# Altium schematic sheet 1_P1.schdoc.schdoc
size 431 x 309 mm; Symbol: Sheet-Symbol_A3; Device: Sheet-Symbol_A3; @Page Name: P1; @Create Date: 2023-12-01; @Page Count: 1; @Page No: 1; @Project Name: TauKeyboard; @Schematic Name: 61key; @Update Date: 2023-12-06; Company: 嘉立创EDA; Page Size: A3; Version: V1.0
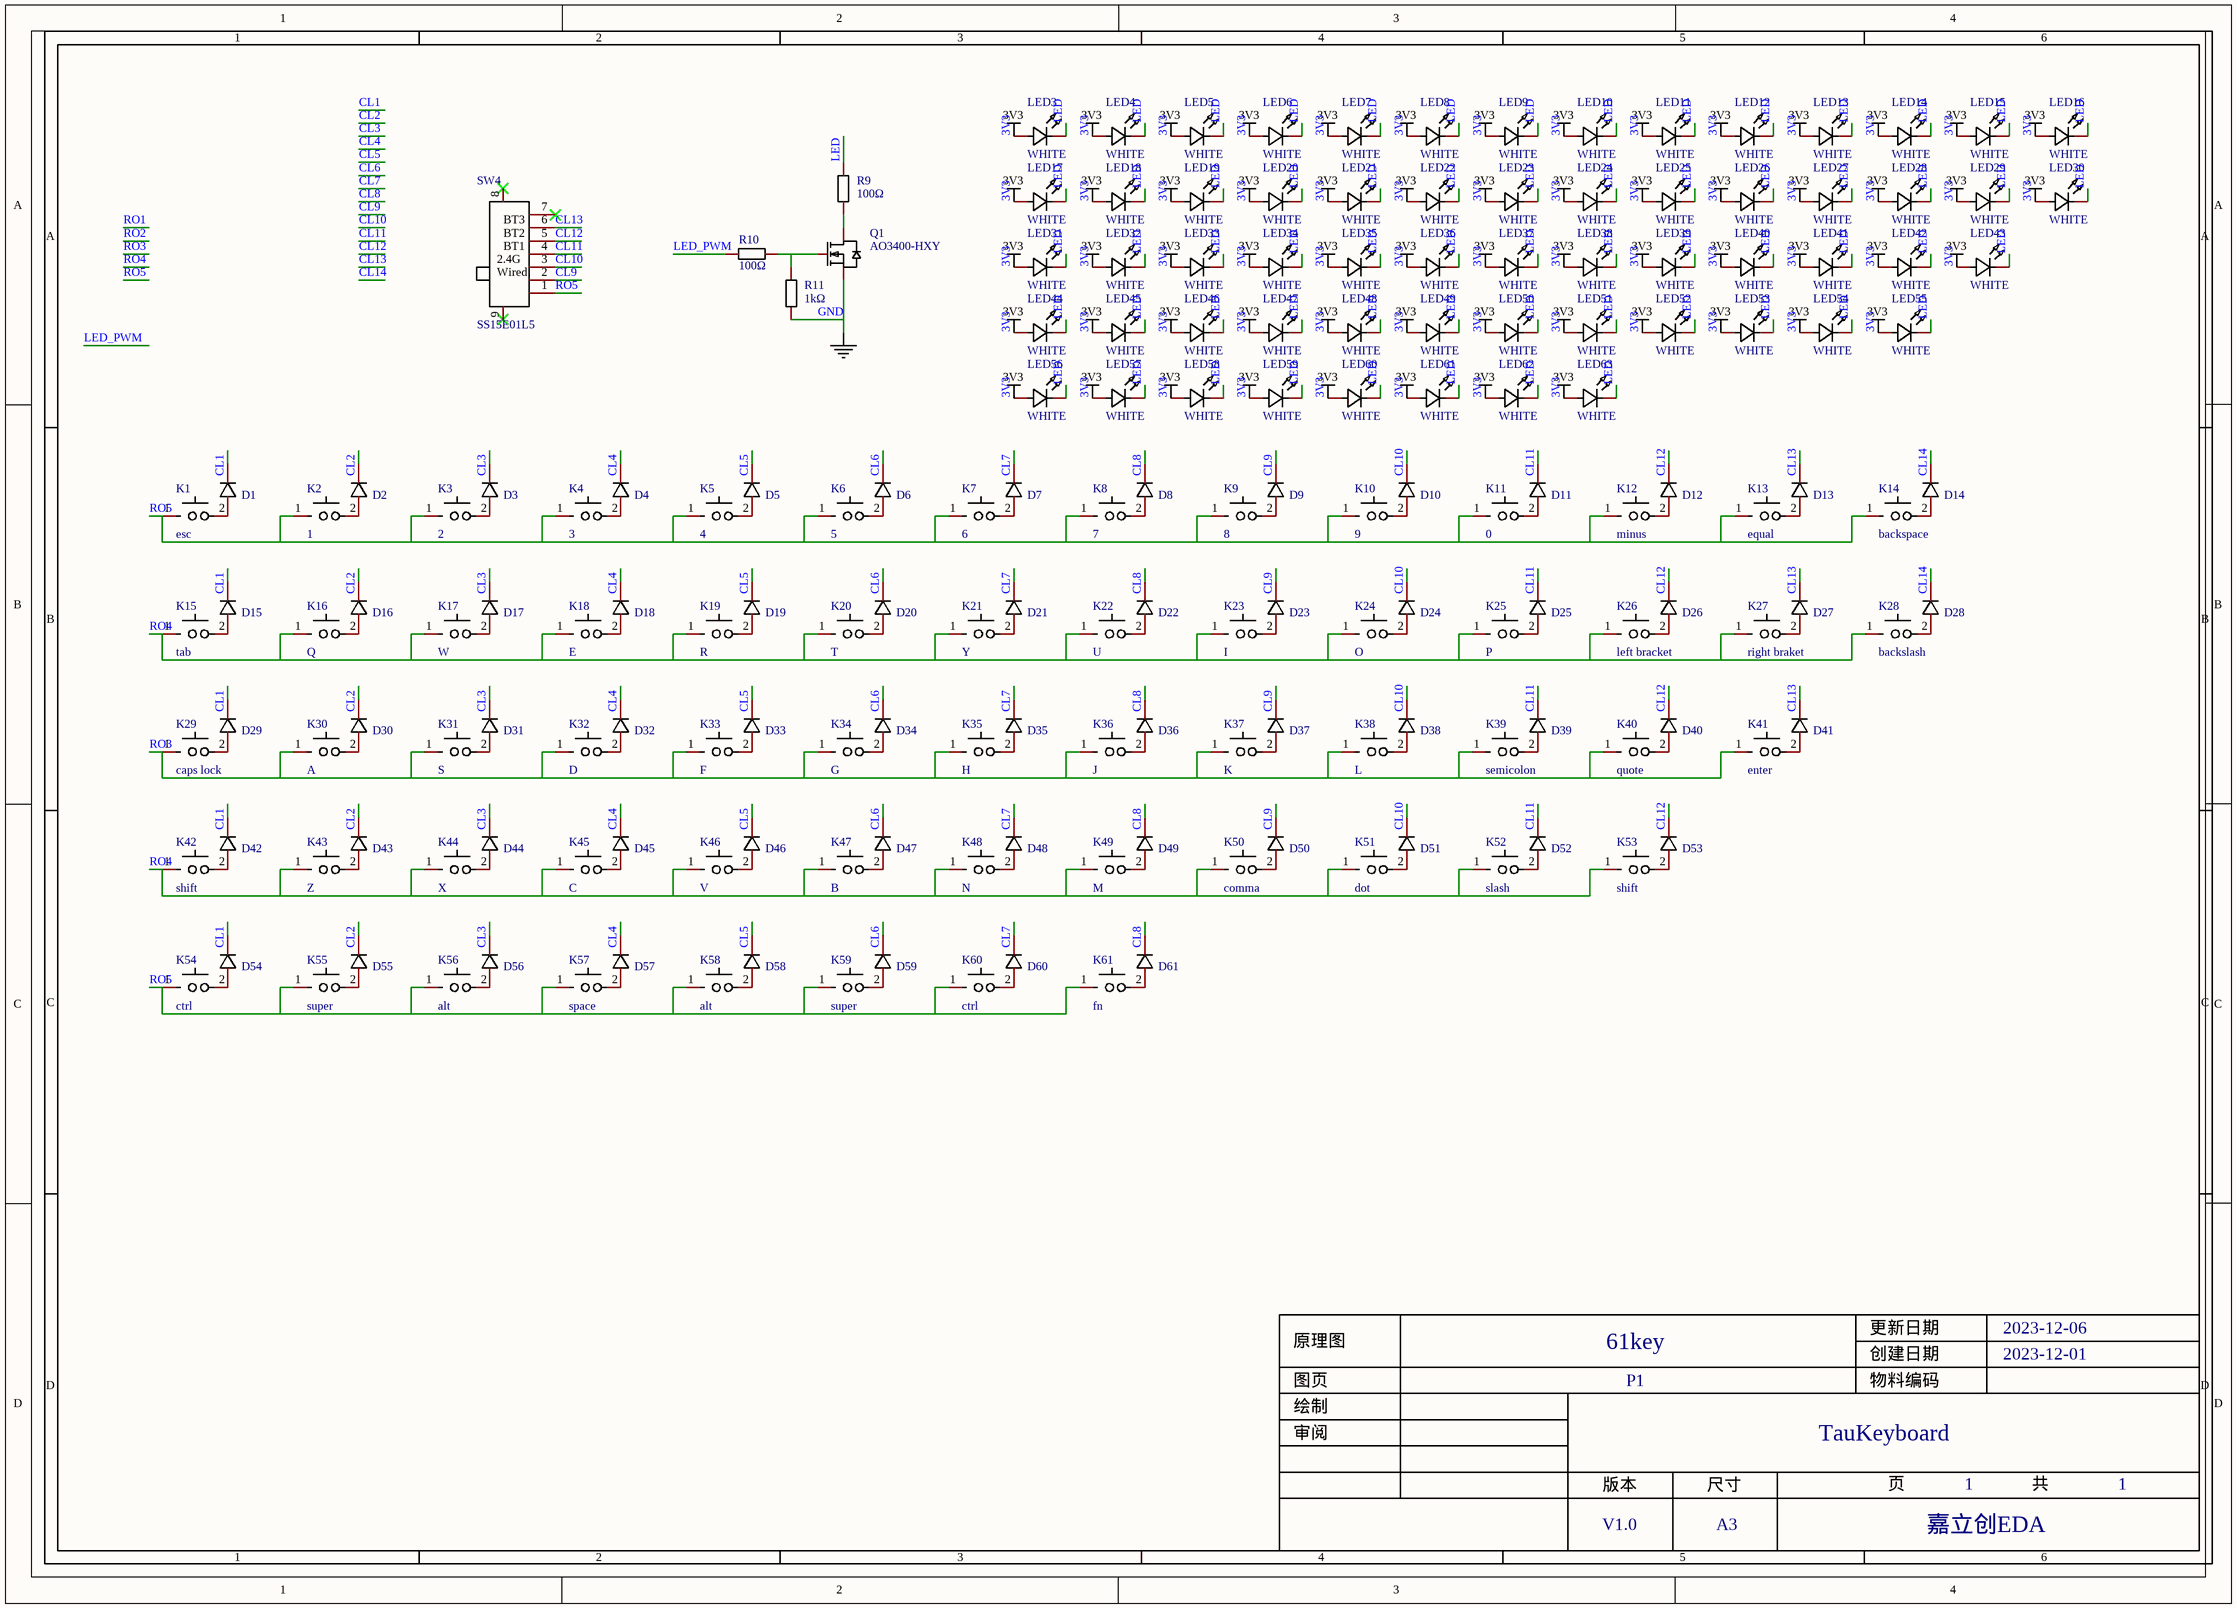
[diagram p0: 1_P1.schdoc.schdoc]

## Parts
D1  1N4148WS_C2128  [SOD-323_L1.8-W1.3-LS2.5-RD]  (value not drawn)
D2  1N4148WS_C2128  [SOD-323_L1.8-W1.3-LS2.5-RD]  (value not drawn)
D3  1N4148WS_C2128  [SOD-323_L1.8-W1.3-LS2.5-RD]  (value not drawn)
D4  1N4148WS_C2128  [SOD-323_L1.8-W1.3-LS2.5-RD]  (value not drawn)
D5  1N4148WS_C2128  [SOD-323_L1.8-W1.3-LS2.5-RD]  (value not drawn)
D6  1N4148WS_C2128  [SOD-323_L1.8-W1.3-LS2.5-RD]  (value not drawn)
D7  1N4148WS_C2128  [SOD-323_L1.8-W1.3-LS2.5-RD]  (value not drawn)
D8  1N4148WS_C2128  [SOD-323_L1.8-W1.3-LS2.5-RD]  (value not drawn)
D9  1N4148WS_C2128  [SOD-323_L1.8-W1.3-LS2.5-RD]  (value not drawn)
D10  1N4148WS_C2128  [SOD-323_L1.8-W1.3-LS2.5-RD]  (value not drawn)
D11  1N4148WS_C2128  [SOD-323_L1.8-W1.3-LS2.5-RD]  (value not drawn)
D12  1N4148WS_C2128  [SOD-323_L1.8-W1.3-LS2.5-RD]  (value not drawn)
D13  1N4148WS_C2128  [SOD-323_L1.8-W1.3-LS2.5-RD]  (value not drawn)
D14  1N4148WS_C2128  [SOD-323_L1.8-W1.3-LS2.5-RD]  (value not drawn)
D15  1N4148WS_C2128  [SOD-323_L1.8-W1.3-LS2.5-RD]  (value not drawn)
D16  1N4148WS_C2128  [SOD-323_L1.8-W1.3-LS2.5-RD]  (value not drawn)
D17  1N4148WS_C2128  [SOD-323_L1.8-W1.3-LS2.5-RD]  (value not drawn)
D18  1N4148WS_C2128  [SOD-323_L1.8-W1.3-LS2.5-RD]  (value not drawn)
D19  1N4148WS_C2128  [SOD-323_L1.8-W1.3-LS2.5-RD]  (value not drawn)
D20  1N4148WS_C2128  [SOD-323_L1.8-W1.3-LS2.5-RD]  (value not drawn)
D21  1N4148WS_C2128  [SOD-323_L1.8-W1.3-LS2.5-RD]  (value not drawn)
D22  1N4148WS_C2128  [SOD-323_L1.8-W1.3-LS2.5-RD]  (value not drawn)
D23  1N4148WS_C2128  [SOD-323_L1.8-W1.3-LS2.5-RD]  (value not drawn)
D24  1N4148WS_C2128  [SOD-323_L1.8-W1.3-LS2.5-RD]  (value not drawn)
D25  1N4148WS_C2128  [SOD-323_L1.8-W1.3-LS2.5-RD]  (value not drawn)
D26  1N4148WS_C2128  [SOD-323_L1.8-W1.3-LS2.5-RD]  (value not drawn)
D27  1N4148WS_C2128  [SOD-323_L1.8-W1.3-LS2.5-RD]  (value not drawn)
D28  1N4148WS_C2128  [SOD-323_L1.8-W1.3-LS2.5-RD]  (value not drawn)
D29  1N4148WS_C2128  [SOD-323_L1.8-W1.3-LS2.5-RD]  (value not drawn)
D30  1N4148WS_C2128  [SOD-323_L1.8-W1.3-LS2.5-RD]  (value not drawn)
D31  1N4148WS_C2128  [SOD-323_L1.8-W1.3-LS2.5-RD]  (value not drawn)
D32  1N4148WS_C2128  [SOD-323_L1.8-W1.3-LS2.5-RD]  (value not drawn)
D33  1N4148WS_C2128  [SOD-323_L1.8-W1.3-LS2.5-RD]  (value not drawn)
D34  1N4148WS_C2128  [SOD-323_L1.8-W1.3-LS2.5-RD]  (value not drawn)
D35  1N4148WS_C2128  [SOD-323_L1.8-W1.3-LS2.5-RD]  (value not drawn)
D36  1N4148WS_C2128  [SOD-323_L1.8-W1.3-LS2.5-RD]  (value not drawn)
D37  1N4148WS_C2128  [SOD-323_L1.8-W1.3-LS2.5-RD]  (value not drawn)
D38  1N4148WS_C2128  [SOD-323_L1.8-W1.3-LS2.5-RD]  (value not drawn)
D39  1N4148WS_C2128  [SOD-323_L1.8-W1.3-LS2.5-RD]  (value not drawn)
D40  1N4148WS_C2128  [SOD-323_L1.8-W1.3-LS2.5-RD]  (value not drawn)
D41  1N4148WS_C2128  [SOD-323_L1.8-W1.3-LS2.5-RD]  (value not drawn)
D42  1N4148WS_C2128  [SOD-323_L1.8-W1.3-LS2.5-RD]  (value not drawn)
D43  1N4148WS_C2128  [SOD-323_L1.8-W1.3-LS2.5-RD]  (value not drawn)
D44  1N4148WS_C2128  [SOD-323_L1.8-W1.3-LS2.5-RD]  (value not drawn)
D45  1N4148WS_C2128  [SOD-323_L1.8-W1.3-LS2.5-RD]  (value not drawn)
D46  1N4148WS_C2128  [SOD-323_L1.8-W1.3-LS2.5-RD]  (value not drawn)
D47  1N4148WS_C2128  [SOD-323_L1.8-W1.3-LS2.5-RD]  (value not drawn)
D48  1N4148WS_C2128  [SOD-323_L1.8-W1.3-LS2.5-RD]  (value not drawn)
D49  1N4148WS_C2128  [SOD-323_L1.8-W1.3-LS2.5-RD]  (value not drawn)
D50  1N4148WS_C2128  [SOD-323_L1.8-W1.3-LS2.5-RD]  (value not drawn)
D51  1N4148WS_C2128  [SOD-323_L1.8-W1.3-LS2.5-RD]  (value not drawn)
D52  1N4148WS_C2128  [SOD-323_L1.8-W1.3-LS2.5-RD]  (value not drawn)
D53  1N4148WS_C2128  [SOD-323_L1.8-W1.3-LS2.5-RD]  (value not drawn)
D54  1N4148WS_C2128  [SOD-323_L1.8-W1.3-LS2.5-RD]  (value not drawn)
D55  1N4148WS_C2128  [SOD-323_L1.8-W1.3-LS2.5-RD]  (value not drawn)
D56  1N4148WS_C2128  [SOD-323_L1.8-W1.3-LS2.5-RD]  (value not drawn)
D57  1N4148WS_C2128  [SOD-323_L1.8-W1.3-LS2.5-RD]  (value not drawn)
D58  1N4148WS_C2128  [SOD-323_L1.8-W1.3-LS2.5-RD]  (value not drawn)
D59  1N4148WS_C2128  [SOD-323_L1.8-W1.3-LS2.5-RD]  (value not drawn)
D60  1N4148WS_C2128  [SOD-323_L1.8-W1.3-LS2.5-RD]  (value not drawn)
D61  1N4148WS_C2128  [SOD-323_L1.8-W1.3-LS2.5-RD]  (value not drawn)
K1  esc  [SMD_KEYBOARD-SW]
K2  1  [SMD_KEYBOARD-SW]
K3  2  [SMD_KEYBOARD-SW]
K4  3  [SMD_KEYBOARD-SW]
K5  4  [SMD_KEYBOARD-SW]
K6  5  [SMD_KEYBOARD-SW]
K7  6  [SMD_KEYBOARD-SW]
K8  7  [SMD_KEYBOARD-SW]
K9  8  [SMD_KEYBOARD-SW]
K10  9  [SMD_KEYBOARD-SW]
K11  0  [SMD_KEYBOARD-SW]
K12  minus  [SMD_KEYBOARD-SW]
K13  equal  [SMD_KEYBOARD-SW]
K14  backspace  [SMD_KEYBOARD-SW]
K15  tab  [SMD_KEYBOARD-SW]
K16  Q  [SMD_KEYBOARD-SW]
K17  W  [SMD_KEYBOARD-SW]
K18  E  [SMD_KEYBOARD-SW]
K19  R  [SMD_KEYBOARD-SW]
K20  T  [SMD_KEYBOARD-SW]
K21  Y  [SMD_KEYBOARD-SW]
K22  U  [SMD_KEYBOARD-SW]
K23  I  [SMD_KEYBOARD-SW]
K24  O  [SMD_KEYBOARD-SW]
K25  P  [SMD_KEYBOARD-SW]
K26  left bracket  [SMD_KEYBOARD-SW]
K27  right braket  [SMD_KEYBOARD-SW]
K28  backslash  [SMD_KEYBOARD-SW]
K29  caps lock  [SMD_KEYBOARD-SW]
K30  A  [SMD_KEYBOARD-SW]
K31  S  [SMD_KEYBOARD-SW]
K32  D  [SMD_KEYBOARD-SW]
K33  F  [SMD_KEYBOARD-SW]
K34  G  [SMD_KEYBOARD-SW]
K35  H  [SMD_KEYBOARD-SW]
K36  J  [SMD_KEYBOARD-SW]
K37  K  [SMD_KEYBOARD-SW]
K38  L  [SMD_KEYBOARD-SW]
K39  semicolon  [SMD_KEYBOARD-SW]
K40  quote  [SMD_KEYBOARD-SW]
K41  enter  [SMD_KEYBOARD-SW]
K42  shift  [SMD_KEYBOARD-SW]
K43  Z  [SMD_KEYBOARD-SW]
K44  X  [SMD_KEYBOARD-SW]
K45  C  [SMD_KEYBOARD-SW]
K46  V  [SMD_KEYBOARD-SW]
K47  B  [SMD_KEYBOARD-SW]
K48  N  [SMD_KEYBOARD-SW]
K49  M  [SMD_KEYBOARD-SW]
K50  comma  [SMD_KEYBOARD-SW]
K51  dot  [SMD_KEYBOARD-SW]
K52  slash  [SMD_KEYBOARD-SW]
K53  shift  [SMD_KEYBOARD-SW]
K54  ctrl  [SMD_KEYBOARD-SW]
K55  super  [SMD_KEYBOARD-SW]
K56  alt  [SMD_KEYBOARD-SW]
K57  space  [SMD_KEYBOARD-SW]
K58  alt  [SMD_KEYBOARD-SW]
K59  super  [SMD_KEYBOARD-SW]
K60  ctrl  [SMD_KEYBOARD-SW]
K61  fn  [SMD_KEYBOARD-SW]
LED3  WHITE  [LED0603-RD]
LED4  WHITE  [LED0603-RD]
LED5  WHITE  [LED0603-RD]
LED6  WHITE  [LED0603-RD]
LED7  WHITE  [LED0603-RD]
LED8  WHITE  [LED0603-RD]
LED9  WHITE  [LED0603-RD]
LED10  WHITE  [LED0603-RD]
LED11  WHITE  [LED0603-RD]
LED12  WHITE  [LED0603-RD]
LED13  WHITE  [LED0603-RD]
LED14  WHITE  [LED0603-RD]
LED15  WHITE  [LED0603-RD]
LED16  WHITE  [LED0603-RD]
LED17  WHITE  [LED0603-RD]
LED18  WHITE  [LED0603-RD]
LED19  WHITE  [LED0603-RD]
LED20  WHITE  [LED0603-RD]
LED21  WHITE  [LED0603-RD]
LED22  WHITE  [LED0603-RD]
LED23  WHITE  [LED0603-RD]
LED24  WHITE  [LED0603-RD]
LED25  WHITE  [LED0603-RD]
LED26  WHITE  [LED0603-RD]
LED27  WHITE  [LED0603-RD]
LED28  WHITE  [LED0603-RD]
LED29  WHITE  [LED0603-RD]
LED30  WHITE  [LED0603-RD]
LED31  WHITE  [LED0603-RD]
LED32  WHITE  [LED0603-RD]
LED33  WHITE  [LED0603-RD]
LED34  WHITE  [LED0603-RD]
LED35  WHITE  [LED0603-RD]
LED36  WHITE  [LED0603-RD]
LED37  WHITE  [LED0603-RD]
LED38  WHITE  [LED0603-RD]
LED39  WHITE  [LED0603-RD]
LED40  WHITE  [LED0603-RD]
LED41  WHITE  [LED0603-RD]
LED42  WHITE  [LED0603-RD]
LED43  WHITE  [LED0603-RD]
LED44  WHITE  [LED0603-RD]
LED45  WHITE  [LED0603-RD]
LED46  WHITE  [LED0603-RD]
LED47  WHITE  [LED0603-RD]
LED48  WHITE  [LED0603-RD]
LED49  WHITE  [LED0603-RD]
LED50  WHITE  [LED0603-RD]
LED51  WHITE  [LED0603-RD]
LED52  WHITE  [LED0603-RD]
LED53  WHITE  [LED0603-RD]
LED54  WHITE  [LED0603-RD]
LED55  WHITE  [LED0603-RD]
LED56  WHITE  [LED0603-RD]
LED57  WHITE  [LED0603-RD]
LED58  WHITE  [LED0603-RD]
LED59  WHITE  [LED0603-RD]
LED60  WHITE  [LED0603-RD]
LED61  WHITE  [LED0603-RD]
LED62  WHITE  [LED0603-RD]
LED63  WHITE  [LED0603-RD]
Q1  AO3400-HXY  [SOT-23_L2.9-W1.3-P1.90-LS2.4-BR]
R9  100Ω  [R0603]
R10  100Ω  [R0603]
R11  1kΩ  [R0603]
SW4  SS15E01L5  [SW-TH_SS15E01L5]

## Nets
3V3: LED3.2(A) LED4.2(A) LED5.2(A) LED6.2(A) LED7.2(A) LED8.2(A) LED9.2(A) LED10.2(A) LED11.2(A) LED12.2(A) LED13.2(A) LED14.2(A) LED15.2(A) LED16.2(A) LED17.2(A) LED18.2(A) LED19.2(A) LED20.2(A) LED21.2(A) LED22.2(A) LED23.2(A) LED24.2(A) LED25.2(A) LED26.2(A) LED27.2(A) LED28.2(A) LED29.2(A) LED30.2(A) LED31.2(A) LED32.2(A) LED33.2(A) LED34.2(A) LED35.2(A) LED36.2(A) LED37.2(A) LED38.2(A) LED39.2(A) LED40.2(A) LED41.2(A) LED42.2(A) LED43.2(A) LED44.2(A) LED45.2(A) LED46.2(A) LED47.2(A) LED48.2(A) LED49.2(A) LED50.2(A) LED51.2(A) LED52.2(A) LED53.2(A) LED54.2(A) LED55.2(A) LED56.2(A) LED57.2(A) LED58.2(A) LED59.2(A) LED60.2(A) LED61.2(A) LED62.2(A) LED63.2(A)
GND: Q1.2(S) R11.1
CL9: SW4.2
CL10: SW4.3
CL11: SW4.4
CL12: SW4.5
CL13: SW4.6
LED: LED3.1(K) LED4.1(K) LED5.1(K) LED6.1(K) LED7.1(K) LED8.1(K) LED9.1(K) LED10.1(K) LED11.1(K) LED12.1(K) LED13.1(K) LED14.1(K) LED15.1(K) LED16.1(K) LED17.1(K) LED18.1(K) LED19.1(K) LED20.1(K) LED21.1(K) LED22.1(K) LED23.1(K) LED24.1(K) LED25.1(K) LED26.1(K) LED27.1(K) LED28.1(K) LED29.1(K) LED30.1(K) LED31.1(K) LED32.1(K) LED33.1(K) LED34.1(K) LED35.1(K) LED36.1(K) LED37.1(K) LED38.1(K) LED39.1(K) LED40.1(K) LED41.1(K) LED42.1(K) LED43.1(K) LED44.1(K) LED45.1(K) LED46.1(K) LED47.1(K) LED48.1(K) LED49.1(K) LED50.1(K) LED51.1(K) LED52.1(K) LED53.1(K) LED54.1(K) LED55.1(K) LED56.1(K) LED57.1(K) LED58.1(K) LED59.1(K) LED60.1(K) LED61.1(K) LED62.1(K) LED63.1(K) R9.2
LED_PWM: R10.1
RO3: K29.1 K30.1 K31.1 K32.1 K33.1 K34.1 K35.1 K36.1 K37.1 K38.1 K39.1 K40.1 K41.1
RO4: K15.1 K16.1 K17.1 K18.1 K19.1 K20.1 K21.1 K22.1 K23.1 K24.1 K25.1 K26.1 K27.1 K28.1 K42.1 K43.1 K44.1 K45.1 K46.1 K47.1 K48.1 K49.1 K50.1 K51.1 K52.1 K53.1
RO5: K1.1 K2.1 K3.1 K4.1 K5.1 K6.1 K7.1 K8.1 K9.1 K10.1 K11.1 K12.1 K13.1 K14.1 K54.1 K55.1 K56.1 K57.1 K58.1 K59.1 K60.1 K61.1 SW4.1
NetD1_2: D1.2(A) K1.2
NetD2_2: D2.2(A) K2.2
NetD3_2: D3.2(A) K3.2
NetD4_2: D4.2(A) K4.2
NetD5_2: D5.2(A) K5.2
NetD6_2: D6.2(A) K6.2
NetD7_2: D7.2(A) K7.2
NetD8_2: D8.2(A) K8.2
NetD9_2: D9.2(A) K9.2
NetD10_2: D10.2(A) K10.2
NetD11_2: D11.2(A) K11.2
NetD12_2: D12.2(A) K12.2
NetD13_2: D13.2(A) K13.2
NetD14_2: D14.2(A) K14.2
NetD15_2: D15.2(A) K15.2
NetD16_2: D16.2(A) K16.2
NetD17_2: D17.2(A) K17.2
NetD18_2: D18.2(A) K18.2
NetD19_2: D19.2(A) K19.2
NetD20_2: D20.2(A) K20.2
NetD21_2: D21.2(A) K21.2
NetD22_2: D22.2(A) K22.2
NetD23_2: D23.2(A) K23.2
NetD24_2: D24.2(A) K24.2
NetD25_2: D25.2(A) K25.2
NetD26_2: D26.2(A) K26.2
NetD27_2: D27.2(A) K27.2
NetD28_2: D28.2(A) K28.2
NetD29_2: D29.2(A) K29.2
NetD30_2: D30.2(A) K30.2
NetD31_2: D31.2(A) K31.2
NetD32_2: D32.2(A) K32.2
NetD33_2: D33.2(A) K33.2
NetD34_2: D34.2(A) K34.2
NetD35_2: D35.2(A) K35.2
NetD36_2: D36.2(A) K36.2
NetD37_2: D37.2(A) K37.2
NetD38_2: D38.2(A) K38.2
NetD39_2: D39.2(A) K39.2
NetD40_2: D40.2(A) K40.2
NetD41_2: D41.2(A) K41.2
NetD42_2: D42.2(A) K42.2
NetD43_2: D43.2(A) K43.2
NetD44_2: D44.2(A) K44.2
NetD45_2: D45.2(A) K45.2
NetD46_2: D46.2(A) K46.2
NetD47_2: D47.2(A) K47.2
NetD48_2: D48.2(A) K48.2
NetD49_2: D49.2(A) K49.2
NetD50_2: D50.2(A) K50.2
NetD51_2: D51.2(A) K51.2
NetD52_2: D52.2(A) K52.2
NetD53_2: D53.2(A) K53.2
NetD54_2: D54.2(A) K54.2
NetD55_2: D55.2(A) K55.2
NetD56_2: D56.2(A) K56.2
NetD57_2: D57.2(A) K57.2
NetD58_2: D58.2(A) K58.2
NetD59_2: D59.2(A) K59.2
NetD60_2: D60.2(A) K60.2
NetD61_2: D61.2(A) K61.2
NetQ1_1: Q1.1(G) R10.2 R11.2
NetQ1_3: Q1.3(D) R9.1

Not connected (* = marked no-connect by the designer): D1 1(K); D2 1(K); D3 1(K); D4 1(K); D5 1(K); D6 1(K); D7 1(K); D8 1(K); D9 1(K); D10 1(K); D11 1(K); D12 1(K); D13 1(K); D14 1(K); D15 1(K); D16 1(K); D17 1(K); D18 1(K); D19 1(K); D20 1(K); D21 1(K); D22 1(K); D23 1(K); D24 1(K); D25 1(K); D26 1(K); D27 1(K); D28 1(K); D29 1(K); D30 1(K); D31 1(K); D32 1(K); D33 1(K); D34 1(K); D35 1(K); D36 1(K); D37 1(K); D38 1(K); D39 1(K); D40 1(K); D41 1(K); D42 1(K); D43 1(K); D44 1(K); D45 1(K); D46 1(K); D47 1(K); D48 1(K); D49 1(K); D50 1(K); D51 1(K); D52 1(K); D53 1(K); D54 1(K); D55 1(K); D56 1(K); D57 1(K); D58 1(K); D59 1(K); D60 1(K); D61 1(K); SW4 7* 8* 9*

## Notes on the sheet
- (near SW4) BT1
- (near SW4) BT2
- (near SW4) BT3
- (near SW4) Wired
- (near SW4) 2.4G
- Labels drawn without touching a wire or pin: CL1, CL2, CL3, CL4, CL5, CL6, CL7, CL8, CL9, CL10, CL11, CL12, CL13, CL14

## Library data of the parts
D1-D61 = 1N4148WS_C2128: 二极管配置:独立式;正向压降(Vf):1.25V@150mA;直流反向耐压(Vr):100V;平均整流电流(Io):150mA;功率:200mW;反向恢复时间(trr):4ns;; Manufacturer: CJ(江苏长电/长晶); Symbol: 1N4148WS T4; Add into BOM: yes; Diode Configuration: 独立式; Reverse Voltage (Vr): 100V; Average Rectified Current (Io): 150mA; Power Dissipation: 200mW; Reverse Leakage Current: 1uA@75V; Reverse Recovery Time (trr): 4ns
K1 K3-K61 = CPG151101S11-16: 轴类型:-;工作电压:2V~12V;针脚数:-;操作力:-;; Manufacturer: Kailh(凯华); Add into BOM: yes; Operating Voltage: 2V~12V; NUMBER: 1
K2 = CPG151101S11-16: 轴类型:-;工作电压:2V~12V;针脚数:-;操作力:-;; Manufacturer: Kailh(凯华); Add into BOM: yes; Operating Voltage: 2V~12V
LED3-LED63 = FC-1608W1-460: 发光颜色:白色;功率:72mW;透镜颜色:雾状黄透镜;发光强度:700mcd~1200mcd;发光角度:130°;工作温度:-30℃~+85℃;; Manufacturer: 国星光电; Add into BOM: yes; Emitted Color: 白色; Forward Voltage (VF): 2.6V~3.6V; Forward Current: 20mA; Power Dissipation: 72mW; Lens Color: 雾状黄透镜; Viewing Angle: 130°
Q1 = AO3400-HXY: 类型:N沟道;阈值电压(Vgs(th)@Id):1.4V@250uA;漏源电压(Vdss):30V;连续漏极电流(Id):5.8A;功率(Pd):1.4W;导通电阻(RDS(on)@Vgs,Id):28mΩ@10V,5.8A;; Manufacturer: HXY MOSFET(华轩阳电子); Symbol: AO3400_C4748804; Add into BOM: yes; Type: N沟道; Drain Source Voltage (Vdss): 30V; Power Dissipation (Pd): 1.4W; Input Capacitance (Ciss@Vds): 825pF@15V
R9 R10 = RC0603FR-07100RL: 电阻类型:厚膜电阻;阻值:100Ω;精度:±1%;功率:100mW;; Manufacturer: YAGEO(国巨); Add into BOM: yes; Tolerance: ±1%; Power(Watts): 100mW; Temperature Coefficient: ±100ppm/℃; Overload Voltage (Max): 75V
R11 = 0603WAF1001T5E: 阻值:1kΩ;精度:±1%;功率:100mW;温度系数:±100ppm/℃;电阻类型:厚膜电阻;; Manufacturer: UNI-ROYAL(厚声); Add into BOM: yes; Tolerance: ±1%; Power(Watts): 100mW; Overload Voltage (Max): 75V
SW4 = SS15E01L5: 额定电流(DC):300mA;额定电压(DC):50V;额定电流(AC):300mA;额定电压(AC):50V;电路结构:单刀五掷;安装方式:弯插;机械寿命:1万次;开关颜色:黑色;; Manufacturer: XKB Connectivity(中国星坤); Add into BOM: yes; Current Rating (DC): 300mA; Voltage Rating (DC): 50V; Circuit: 单刀五掷; Mechanical Life: 1万次; Actuator Color: 黑色; Actuator Style: 矩形柱状; Pin Style: PC引脚; Switch Length: 22mm; Switch Width: 5.1mm; Switch Height: 7.4mm; NAME: 2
